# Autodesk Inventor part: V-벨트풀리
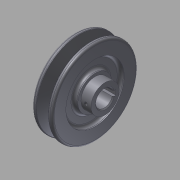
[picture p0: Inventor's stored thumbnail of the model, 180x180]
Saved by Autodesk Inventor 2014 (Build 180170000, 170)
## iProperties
Company: 한국ATC센터
Created: 2014-07
Part Number: V-벨트풀리
Document SubType Name: Modeling
Designer: KYOUNG IL JANG
Density: 7.87 g/cm^3
Material: 강철, 탄소
Mass: 593.766 g
Surface Area: 234.122 cm^2
Volume: 75.4468 cm^3
Appearance: 강철
Author: KYOUNG IL JANG
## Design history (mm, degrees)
sketch "스케치1"
  geometry: L1 (-15, 0)-(15, 0); L2 (-15, 0)-(-15, 17); L3 (-15, 17)-(-11, 17); L4 (-11, 17)-(-11, 29); L5 (-11, 29)-(-15, 29); L6 (-15, 29)-(-15, 42.5); L7 (-15, 42.5)-(-10.976, 42.5); L8 (-10.976, 42.5)-(-7.154, 30); L9 (-7.154, 30)-(-2.846, 30); L10 (-2.846, 30)-(0.976, 42.5); L11 (0.976, 42.5)-(5, 42.5); L12 (5, 42.5)-(5, 29); L13 (5, 29)-(1, 29); L14 (1, 29)-(1, 17); L15 (1, 17)-(5, 17); L16 (5, 17)-(5, 14); L17 (5, 14)-(15, 14); L18 (15, 14)-(15, 0); L19 (-9.6, 38)-(-0.4, 38); 2 further points
  constraints: 38 end point, 11 parallel, 7 collinear, 3 equal length, 3 perpendicular, 2 point on line, 1 coincident, 1 horizontal, 1 midpoint
  dimensions: "d0" = 30 distance of L1.start L1.end; "d1" = 4.5 distance between parallel lines of L7 L19; "d2" = 8 distance between parallel lines of L9 L19; "d3" = 9.2 distance of L19.start L19.end; "d4" = 34 deg angle of L10 L8; "d5" = 20 distance between parallel lines of L12 L6; "d6" = 76 diameter of L19 L1; "d7" = 4 distance of L2.end L3.end; "d8" = 34 diameter of L3 L1; "d9" = 58 diameter of L5 L1; "d10" = 28 diameter of L17 L1
revolve "회전1" sketch "스케치1" stored, may be unused: angle "d11" = 90 deg
sketch "스케치2"
  geometry: L1 (-2.5, 8.124)-(-2.5, 10.8); L2 (-2.5, 10.8)-(2.5, 10.8); L3 (2.5, 10.8)-(2.5, 8.124); A1 r 8.5 centre (0, 0) between (-2.5, 8.124) and (2.5, 8.124); 1 further point
  constraints: 6 end point, 2 parallel, 2 point on circle, 1 centre point, 1 coincident, 1 horizontal, 1 vertical
  dimensions: "d12" = 17 diameter of A1; "d13" = 5 distance of L1.end L2.end; "d14" = 19.3 dimension on A1 L2 (computed from d12)
extrude "돌출1" cut sketch "스케치2" stored distance "d15" = 10; taper "d16" = 0 deg
chamfer "모따기1" distance "d17" = 1; stored, may be unused: second distance "d18" = 2, angle "d19" = 45 deg
node "작업 평면1"
sketch "스케치3"
  geometry: L1 (5, -14)-(5, 14) reference; 3 further points
  constraints: 1 horizontal alignment, 1 midpoint
  dimensions: "d20" = 5 distance from line of L1 point (0, 0)
hole "구멍1" sketch "스케치3" at (0, 0) diameter "d21" = 3.242; stored, may be unused: countersink angle "d25" = 90 deg, drill point angle "d27" = 118 deg; dims "d22" = 6, "d23" = 4, "d24" = 2, "d26" = 8
fillet "모깎기1" dims "d28" = 3, "d29" = 2, "d30" = 0.5, "d31" = 1
node "솔리드1"
